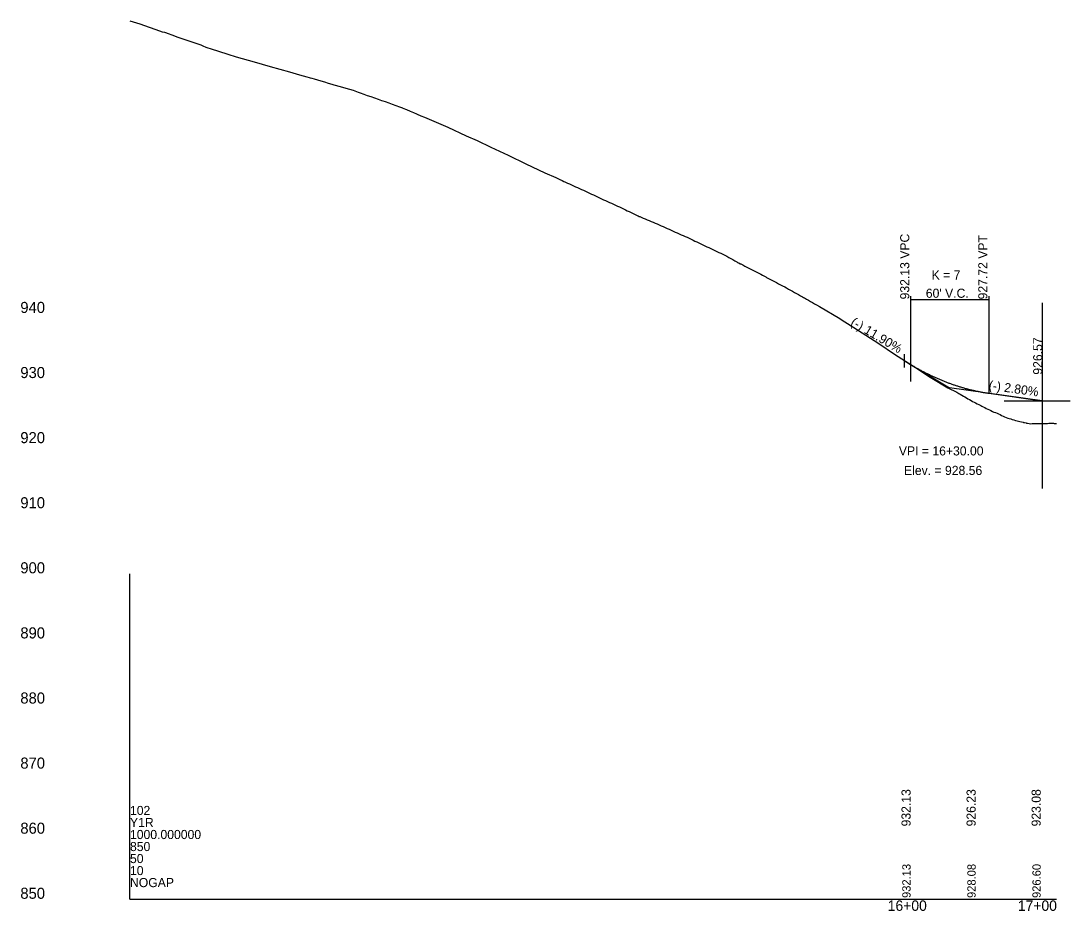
# Model space of a CAD drawing. Extents: x 1558113 to 1562835, y 1129435 to 1135883.
# Drawn here: x 1558113 to 1558919, y 1131435 to 1132118 of the extents above; entities that cross this region are included whole.
import ezdxf

# ---------------------------------------------------------------- set-up
doc = ezdxf.new("R2010")
doc.units = 0
for name, color, linetype in [('BR_USER NOTES', 7, 'Continuous'), ('RD_DDB_ElevTX', 7, 'Continuous'), ('RD_DDB_GradeTX', 7, 'Continuous'), ('RD_DDB_Profile_EX', 7, 'Continuous'), ('RD_DDB_Profile_Lbl', 7, 'Continuous'), ('RD_DDB_Profile_PR', 7, 'Continuous'), ('RD_DDB_StaTX', 7, 'Continuous'), ('RD_DDB_StripGrade', 7, 'Continuous'), ('RD_DDB_VCLbl', 7, 'Continuous'), ('RD_GPK_Profile_Cell', 7, 'Continuous')]:
    doc.layers.add(name, color=color, linetype=linetype)

msp = doc.modelspace()

# ---------------------------------------------------------------- linework, layer by layer
at = {"layer": 'BR_USER NOTES'}
for p, q in [((1558897.57, 1131901.84), (1558897.57, 1131759.19)), ((1558796.37, 1131870.61), (1558796.37, 1131841.44)), ((1558791.37, 1131862.56), (1558791.37, 1131852.19)), ((1558791.37, 1131857.69), (1558796.37, 1131854.5)), ((1558868.28, 1131826.69), (1558918.89, 1131826.69))]:
    msp.add_line(p, q, dxfattribs=at)
at = {"layer": 'RD_DDB_GradeTX'}
for p in [(1558796.37, 1131854.5), (1558897.57, 1131826.69)]:
    msp.add_line(p, (1558826.37, 1131836.65), dxfattribs=at)
at = {"layer": 'RD_DDB_Profile_EX'}
msp.add_lwpolyline([(1558196.37, 1132118.36), (1558203.9, 1132116.07), (1558219.08, 1132110.78), (1558221.17, 1132110.16), (1558222.79, 1132109.7), (1558223.57, 1132109.5), (1558230.49, 1132106.93), (1558232.3, 1132106.1), (1558250.73, 1132100.15), (1558252.36, 1132099.39), (1558254.76, 1132098.38), (1558256.21, 1132097.79), (1558257.87, 1132097.11), (1558271.59, 1132092.98), (1558278.01, 1132090.78), (1558291.77, 1132086.88), (1558303.99, 1132083.48), (1558318.88, 1132079.25), (1558326.74, 1132077.06), (1558329.48, 1132076.3), (1558332.22, 1132075.54), (1558333.97, 1132075.05), (1558334.96, 1132074.76), (1558336.24, 1132074.39), (1558337.82, 1132073.93), (1558340.44, 1132073.16), (1558343.18, 1132072.35), (1558345.92, 1132071.54), (1558348.66, 1132070.73), (1558351.39, 1132069.92), (1558353, 1132069.45), (1558354.13, 1132069.12), (1558356.87, 1132068.32), (1558359.61, 1132067.52), (1558362.35, 1132066.72), (1558365.09, 1132065.91), (1558367.83, 1132065.11), (1558370.57, 1132064.15), (1558371.64, 1132063.78), (1558373.31, 1132063.18), (1558376.05, 1132062.19), (1558378.78, 1132061.23), (1558381.52, 1132060.28), (1558384.26, 1132059.32), (1558387, 1132058.36), (1558389.74, 1132057.41), (1558390.68, 1132057.08), (1558392.48, 1132056.42), (1558395.22, 1132055.42), (1558397.96, 1132054.42), (1558400.7, 1132053.42), (1558403.44, 1132052.42), (1558405.73, 1132051.57), (1558406.17, 1132051.39), (1558408.91, 1132050.26), (1558411.65, 1132049.12), (1558414.39, 1132047.98), (1558416.46, 1132047.12), (1558417.13, 1132046.83), (1558419.87, 1132045.64), (1558422.61, 1132044.45), (1558428.01, 1132042.1), (1558440.56, 1132036.74), (1558454.87, 1132030.26), (1558463.11, 1132026.53), (1558473.7, 1132021.49), (1558487.1, 1132015.29), (1558500.68, 1132008.65), (1558515.2, 1132001.82), (1558523.57, 1131998.02), (1558525.1, 1131997.32), (1558526.63, 1131996.62), (1558528.44, 1131995.79), (1558529.83, 1131995.17), (1558530.54, 1131994.85), (1558531.22, 1131994.55), (1558532.75, 1131993.87), (1558534.28, 1131993.18), (1558535.81, 1131992.49), (1558537.34, 1131991.8), (1558538.86, 1131991.1), (1558540.39, 1131990.41), (1558541.92, 1131989.71), (1558543.45, 1131989.01), (1558544.28, 1131988.63), (1558544.98, 1131988.31), (1558546.51, 1131987.6), (1558548.04, 1131986.89), (1558549.57, 1131986.18), (1558551.1, 1131985.46), (1558552.63, 1131984.75), (1558554.16, 1131984.03), (1558555.69, 1131983.31), (1558557.22, 1131982.59), (1558558.75, 1131981.87), (1558560.42, 1131981.08), (1558561.81, 1131980.45), (1558563.34, 1131979.75), (1558564.87, 1131979.05), (1558566.4, 1131978.35), (1558567.93, 1131977.65), (1558569.46, 1131976.94), (1558570.99, 1131976.24), (1558572.52, 1131975.53), (1558574.21, 1131974.74), (1558575.57, 1131974.1), (1558577.1, 1131973.37), (1558578.63, 1131972.64), (1558580.16, 1131971.91), (1558581.69, 1131971.18), (1558583.22, 1131970.45), (1558584.75, 1131969.72), (1558586.28, 1131968.98), (1558587.01, 1131968.63), (1558587.81, 1131968.29), (1558588.19, 1131968.13), (1558589.34, 1131967.65), (1558590.87, 1131967), (1558592.4, 1131966.35), (1558593.93, 1131965.7), (1558595.46, 1131965.05), (1558596.99, 1131964.4), (1558598.52, 1131963.74), (1558600.05, 1131963.09), (1558601.58, 1131962.43), (1558602.14, 1131962.19), (1558603.11, 1131961.76), (1558604.64, 1131961.08), (1558606.17, 1131960.4), (1558607.7, 1131959.72), (1558609.23, 1131959.03), (1558610.75, 1131958.35), (1558612.28, 1131957.66), (1558613.81, 1131956.97), (1558615.34, 1131956.28), (1558616.87, 1131955.59), (1558618.4, 1131954.9), (1558619.93, 1131954.23), (1558621.46, 1131953.56), (1558622.99, 1131952.89), (1558624.52, 1131952.21), (1558626.05, 1131951.5), (1558627.58, 1131950.79), (1558629.11, 1131950.07), (1558630.64, 1131949.35), (1558632.17, 1131948.63), (1558633.7, 1131947.91), (1558635.23, 1131947.19), (1558636.76, 1131946.47), (1558638.29, 1131945.74), (1558639.82, 1131945.01), (1558641.35, 1131944.28), (1558642.88, 1131943.54), (1558644.41, 1131942.8), (1558645.94, 1131942.06), (1558647.46, 1131941.32), (1558648.99, 1131940.58), (1558649.72, 1131940.23), (1558650.52, 1131939.93), (1558652.05, 1131939.31), (1558653.58, 1131938.47), (1558655.11, 1131937.62), (1558656.64, 1131936.77), (1558658.17, 1131935.91), (1558659.7, 1131935.06), (1558661.23, 1131934.21), (1558662.76, 1131933.34), (1558663.38, 1131932.89), (1558664.29, 1131932.48), (1558665.46, 1131931.94), (1558665.82, 1131931.75), (1558667.35, 1131930.95), (1558668.88, 1131930.14), (1558670.41, 1131929.34), (1558671.94, 1131928.53), (1558673.47, 1131927.73), (1558675, 1131926.92), (1558676.53, 1131926.12), (1558678.06, 1131925.34), (1558679.59, 1131924.57), (1558681.12, 1131923.79), (1558682.64, 1131923.02), (1558684.17, 1131922.24), (1558684.98, 1131921.81), (1558685.7, 1131921.43), (1558687.23, 1131920.62), (1558688.76, 1131919.82), (1558690.29, 1131919.01), (1558691.82, 1131918.2), (1558693.35, 1131917.39), (1558694.88, 1131916.58), (1558696.41, 1131915.77), (1558697.94, 1131914.96), (1558699.59, 1131914.09), (1558701, 1131913.31), (1558702.53, 1131912.46), (1558704.06, 1131911.61), (1558705.59, 1131910.76), (1558707.12, 1131909.9), (1558708.65, 1131909.05), (1558710.18, 1131908.2), (1558711.71, 1131907.34), (1558713.24, 1131906.49), (1558713.98, 1131906.08), (1558714.77, 1131905.62), (1558716.3, 1131904.74), (1558717.83, 1131903.85), (1558719.35, 1131902.97), (1558720.88, 1131902.08), (1558722.41, 1131901.2), (1558723.94, 1131900.31), (1558726.3, 1131898.95), (1558741.94, 1131889.76), (1558742.96, 1131889.11), (1558755.67, 1131881.07), (1558771.93, 1131870.54), (1558783.97, 1131862.4), (1558800.03, 1131852.17), (1558811.51, 1131844.8), (1558825.09, 1131836.48), (1558831.83, 1131833.19), (1558833.4, 1131832.28), (1558834.58, 1131831.6), (1558835.75, 1131830.92), (1558836.93, 1131830.24), (1558838.1, 1131829.56), (1558839.28, 1131828.87), (1558840.45, 1131828.19), (1558841.63, 1131827.51), (1558842.8, 1131826.82), (1558843.98, 1131826.16), (1558845.15, 1131825.57), (1558846.33, 1131824.99), (1558847.5, 1131824.4), (1558848.68, 1131823.81), (1558849.85, 1131823.23), (1558850.47, 1131822.92), (1558851.03, 1131822.61), (1558852.2, 1131821.97), (1558853.38, 1131821.35), (1558854.55, 1131820.83), (1558855.73, 1131820.3), (1558857.1, 1131819.68), (1558858.08, 1131819.15), (1558859.26, 1131818.5), (1558859.78, 1131818.21), (1558860.43, 1131817.97), (1558861.61, 1131817.52), (1558862.78, 1131817.07), (1558863.96, 1131816.6), (1558865.13, 1131816.01), (1558866.31, 1131815.43), (1558867.51, 1131814.83), (1558868.66, 1131814.36), (1558869.83, 1131813.88), (1558871.01, 1131813.41), (1558872.18, 1131813.05), (1558873.36, 1131812.68), (1558874.53, 1131812.32), (1558875.75, 1131811.94), (1558876.88, 1131811.57), (1558878.22, 1131811.14), (1558879.23, 1131810.92), (1558880.41, 1131810.66), (1558881.58, 1131810.39), (1558882.76, 1131810.13), (1558883.08, 1131810.06), (1558883.93, 1131809.88), (1558885.11, 1131809.64), (1558885.57, 1131809.55), (1558886.28, 1131809.42), (1558887.46, 1131809.21), (1558888.63, 1131809.05), (1558889.81, 1131809.08), (1558890.98, 1131809.1), (1558892.16, 1131809.13), (1558893.33, 1131809.16), (1558894.51, 1131809.18), (1558895.68, 1131809.2), (1558896.86, 1131809.23), (1558898.03, 1131809.25), (1558899.21, 1131809.27), (1558900.38, 1131809.29), (1558901.56, 1131809.3), (1558902.73, 1131809.32), (1558903.93, 1131809.33), (1558904.25, 1131809.38), (1558905.08, 1131809.37), (1558906.2, 1131809.35), (1558906.83, 1131809.26), (1558907.43, 1131809.2), (1558908.61, 1131809.09)], dxfattribs=at)
at = {"layer": 'RD_DDB_Profile_PR'}
msp.add_line((1558856.37, 1131832.45), (1558897.57, 1131826.69), dxfattribs=at)
msp.add_spline([(1558796.37, 1131854.5), (1558797.57, 1131853.79), (1558798.77, 1131853.1), (1558799.97, 1131852.41), (1558801.17, 1131851.73), (1558802.37, 1131851.07), (1558803.57, 1131850.41), (1558804.77, 1131849.77), (1558805.97, 1131849.14), (1558807.17, 1131848.52), (1558808.37, 1131847.91), (1558809.57, 1131847.31), (1558810.77, 1131846.72), (1558811.97, 1131846.14), (1558813.17, 1131845.58), (1558814.37, 1131845.02), (1558815.57, 1131844.48), (1558816.77, 1131843.94), (1558817.97, 1131843.42), (1558819.17, 1131842.91), (1558820.37, 1131842.41), (1558821.57, 1131841.92), (1558822.77, 1131841.44), (1558823.97, 1131840.97), (1558825.17, 1131840.51), (1558826.37, 1131840.07), (1558827.57, 1131839.63), (1558828.77, 1131839.21), (1558829.97, 1131838.79), (1558831.17, 1131838.39), (1558832.37, 1131838), (1558833.57, 1131837.62), (1558834.77, 1131837.25), (1558835.97, 1131836.89), (1558837.17, 1131836.54), (1558838.37, 1131836.2), (1558839.57, 1131835.88), (1558840.77, 1131835.56), (1558841.97, 1131835.26), (1558843.17, 1131834.96), (1558844.37, 1131834.68), (1558845.57, 1131834.41), (1558846.77, 1131834.15), (1558847.97, 1131833.9), (1558849.17, 1131833.66), (1558850.37, 1131833.43), (1558851.57, 1131833.21), (1558852.77, 1131833.01), (1558853.97, 1131832.81), (1558855.17, 1131832.63), (1558856.37, 1131832.45)], degree=3, dxfattribs=at)
at = {"layer": 'RD_DDB_VCLbl'}
for p, q in [((1558796.37, 1131907), (1558796.37, 1131854.5)), ((1558796.37, 1131904.5), (1558856.37, 1131904.5)), ((1558856.37, 1131907), (1558856.37, 1131832.45))]:
    msp.add_line(p, q, dxfattribs=at)
at = {"layer": 'RD_GPK_Profile_Cell'}
for q in [(1558196.37, 1131693.84), (1558908.61, 1131443.84), (1558196.37, 1131443.84)]:
    msp.add_line((1558196.37, 1131443.84), q, dxfattribs=at)

# ---------------------------------------------------------------- texts
at = {"layer": 'RD_DDB_ElevTX'}
for s, p in [('940', (1558112.09, 1131894.09)), ('930', (1558112.09, 1131844.09)), ('920', (1558112.09, 1131794.09)), ('910', (1558112.09, 1131744.09)), ('900', (1558112.09, 1131694.09)), ('890', (1558112.09, 1131644.09)), ('880', (1558112.09, 1131594.09)), ('870', (1558112.09, 1131544.09)), ('860', (1558112.09, 1131494.09)), ('850', (1558112.09, 1131444.09))]:
    msp.add_text(s, height=8.5, dxfattribs=at).set_placement(p)
at = {"layer": 'RD_DDB_GradeTX'}
for s, rotation, p in [('(-) 11.90%', 329.25119, (1558749.68, 1131885.18)), ('(-) 2.80%', 352.03039, (1558856.05, 1131835.26))]:
    msp.add_text(s, height=7, rotation=rotation, dxfattribs=at).set_placement(p)
at = {"layer": 'RD_DDB_Profile_Lbl'}
msp.add_text('926.57', height=7, rotation=90, dxfattribs=at).set_placement((1558897.57, 1131846.69))
for s, p in [('VPI = 16+30.00', (1558787.34, 1131784.65)), ('Elev. = 928.56', (1558791.31, 1131769.65))]:
    msp.add_text(s, height=7, dxfattribs=at).set_placement(p)
at = {"layer": 'RD_DDB_StaTX'}
for s, p in [('16+00', (1558778.77, 1131434.84)), ('17+00', (1558878.77, 1131434.84))]:
    msp.add_text(s, height=8, dxfattribs=at).set_placement(p)
at = {"layer": 'RD_DDB_StripGrade'}
for s, height, p in [('932.13 VPC', 7, (1558795.37, 1131904.5)), ('927.72 VPT', 7, (1558855.37, 1131904.5)), ('932.13', 7, (1558796.37, 1131499.68)), ('926.23', 7, (1558846.37, 1131499.68)), ('923.08', 7, (1558896.37, 1131499.68)), ('932.13', 6.4, (1558796.37, 1131444.71)), ('928.08', 6.4, (1558846.37, 1131444.71)), ('926.60', 6.4, (1558896.37, 1131444.71))]:
    msp.add_text(s, height=height, rotation=90, dxfattribs=at).set_placement(p)
at = {"layer": 'RD_DDB_VCLbl'}
for s, p in [('K = 7', (1558812.52, 1131919.75)), ("60' V.C.", (1558808.05, 1131905.75))]:
    msp.add_text(s, height=7, dxfattribs=at).set_placement(p)
at = {"layer": 'RD_GPK_Profile_Cell'}
for s, p in [('102', (1558196.37, 1131508.45)), ('Y1R', (1558196.37, 1131499.22)), ('1000.000000', (1558196.37, 1131489.99)), ('850', (1558196.37, 1131480.76)), ('50', (1558196.37, 1131471.53)), ('10', (1558196.37, 1131462.3)), ('NOGAP', (1558196.37, 1131453.07))]:
    msp.add_text(s, height=7, dxfattribs=at).set_placement(p)

doc.saveas('drawing.dxf')
